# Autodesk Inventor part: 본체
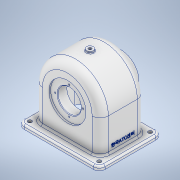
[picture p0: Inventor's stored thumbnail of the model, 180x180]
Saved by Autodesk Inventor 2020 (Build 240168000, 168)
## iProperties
Created: 2022-09
Part Number: 본체
Material: 알루미늄 6061
Document SubType Name: Modeling
Designer: Administrator
Density: 2.7 g/cm^3
Appearance: 알루미늄 - 평지
Mass: 987.342 g
Surface Area: 1165.69 cm^2
Volume: 365.682 cm^3
Author: Administrator
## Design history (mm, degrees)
sketch "스케치1"
  geometry: L1 (-60, 54)-(60, 54); L2 (70, 44)-(70, -44); L3 (60, -54)-(-60, -54); L4 (-70, -44)-(-70, 44); C1 r 3.3 at (-60, 44); C2 r 3.3 at (60, 44); C3 r 3.3 at (60, -44); C4 r 3.3 at (-60, -44); A1 r 10 centre (-60, 44) between (-60, 54) and (-70, 44); A2 r 10 centre (-60, -44) between (-70, -44) and (-60, -54); A3 r 10 centre (60, -44) between (60, -54) and (70, -44); A4 r 10 centre (60, 44) between (70, 44) and (60, 54); 4 further points
  constraints: 8 centre point, 8 end point, 8 point on circle, 8 tangent, 6 point on line, 4 coincident, 3 equal radius, 2 parallel, 1 horizontal, 1 perpendicular
  dimensions: "d0" = 140 distance of point (70, -54) point (-70, -54); "d1" = 108 distance of point (70, 54) point (70, -54); "d2" = 10 radius of A1; "d3" = 6.6 diameter of C1; "d4" = 6.6 diameter of C2; "d5" = 6.6 diameter of C3; "d6" = 6.6 diameter of C4
extrude "돌출1" new body sketch "스케치1" distance "d7" = 7; taper "d8" = 0 deg
sketch "스케치2"
  geometry: L1 (-60, 0)-(60, 0) reference; L2 (-60, 7)-(60, 7) reference; L3 (-63.3, 7)-(-56.7, 7) reference; L4 (-56.7, 64.001)-(-56.7, 7); L5 (57.3, 64)-(57.3, 5.235); A1 r 57 centre (0.3, 64) between (0.6, 120.999) and (-56.7, 64.001); 2 further points
  constraints: 4 end point, 3 point on circle, 1 centre point, 1 perpendicular, 1 tangent, 1 vertical
  dimensions: "d9" = 57 radius of A1; "d10" = 64 distance from line of L1 A1.centre
extrude "돌출2" new body sketch "스케치2" stored distance "d11" = 78; taper "d12" = 0 deg
feature "쉘1" dims "d13" = 5
sketch "스케치3"
  geometry: L1 (57, 7)-(57, 64.001); L2 (-57, 64)-(-57, 7); L3 (-57, 7)-(57, 7); L4 (-60, 0)-(60, 0) reference; C1 r 32 at (0, 64); A1 r 57 centre (0, 64) between (57, 64.001) and (-57, 64); 2 further points
  constraints: 6 end point, 2 centre point, 2 point on circle, 1 coincident, 1 midpoint, 1 vertical alignment
  dimensions: "d14" = 32 radius of C1
sketch "스케치4"
  geometry: C1 r 31 at (-0.3, -64); A1 r 57 centre (-0.3, -64) between (-57.3, -64) and (56.7, -64.001) reference; 1 further point
  constraints: 1 centre point, 1 coincident
  dimensions: "d15" = 62 diameter of C1
extrude "돌출3" join sketch "스케치4" distance "d16" = 15; taper "d17" = 0 deg
feature "결합1"
  node "솔리드2"
sketch "스케치5"
  geometry: C1 r 20 at (0.3, 0); 1 further point
  constraints: 1 centre point
  dimensions: "d18" = 40 diameter of C1
extrude "돌출4" cut sketch "스케치5" distance "d19" = 16; taper "d20" = 0 deg
fillet "모깎기1" dims "d21" = 0.6
sketch "스케치6"
  geometry: C1 r 19.4 at (0, 0) reference; C2 r 17.5 at (0, 0); 1 further point
  constraints: 1 centre point, 1 coincident
  dimensions: "d22" = 35 diameter of C2
extrude "돌출5" cut sketch "스케치6" distance "d23" = 16; taper "d24" = 0 deg
chamfer "모따기1" distance "d25" = 1; stored, may be unused: second distance "d26" = 2, angle "d27" = 45 deg
node "작업 평면1"
sketch "스케치9"
  geometry: L1 (-34, 116)-(-34, 64) reference; L2 (-34, 100.083)-(-20, 92); L3 (-34, 64)-(-34, 12) reference; L4 (-50.325, 64)-(9.78, 64); L5 (-34, 64)-(34, 64) reference; L6 (-20, 92)-(-20, 64); 4 further points
  constraints: 6 end point, 3 point on line, 1 perpendicular
  dimensions: "d35" = 60 deg angle of L6 L2; "d36" = 56 diameter of L2.end L4; "d37" = 14 distance between parallel lines of L1 L6
revolve "회전1" sketch "스케치9" stored, may be unused: angle "d38" = 90 deg
sketch "스케치10"
  geometry: C1 r 28 at (0, 0) reference; C2 r 20 at (0, 0); 1 further point
  constraints: 1 centre point, 1 coincident
  dimensions: "d39" = 40 diameter of C2
extrude "돌출8" cut sketch "스케치10" distance "d40" = 16; taper "d41" = 0 deg
extrude "돌출9" cut sketch "스케치3" stored distance "d42" = 3.25; taper "d43" = 0 deg
fillet "모깎기2" dims "d44" = 14
fillet "모깎기3" dims "d45" = 3
node "작업 평면2"
node "작업 평면3"
sketch "스케치12"
  geometry: C1 r 6 at (0, 0); 1 further point
  constraints: 1 centre point, 1 coincident
  dimensions: "d55" = 12 diameter of C1
extrude "돌출10" join sketch "스케치12" stored distance "d56" = 16; taper "d57" = 0 deg
fillet "모깎기4" dims "d58" = 1
sketch "스케치13"
  geometry: C1 r 6 at (0, 0) reference; 2 further points
  constraints: 1 coincident
hole "구멍2" sketch "스케치13" at (0, 0) diameter "d59" = 5.1881; stored, may be unused: countersink angle "d63" = 90 deg, drill point angle "d65" = 118 deg; dims "d60" = 12, "d61" = 4, "d62" = 2, "d64" = 16
sketch "스케치14"
  geometry: L1 (0.941, 15.484)-(0.941, 34.516); L2 (0.941, 34.516)-(93.06, 34.516); L3 (93.06, 34.516)-(93.06, 15.484); L4 (93.06, 15.484)-(0.941, 15.484); L5 (0, -14)-(54.001, -14) reference; L6 (64.001, -19)-(64.001, 69) reference; 3 further points
  constraints: 2 midpoint, 2 other
  dimensions: "d66" = 39 distance from line of L5 point (0.941, 25); "d67" = 17 distance from line of L6 point (47.001, 34.516)
feature "엠보싱1" sketch "스케치14" dims "d0" = 140, "d1" = 108, "d2" = 10, "d3" = 6.6, "d4" = 6.6, "d5" = 6.6, "d6" = 6.6, "d68" = 0.5, "d69" = 0
chamfer "모따기2" distance "d70" = 1; stored, may be unused: second distance "d71" = 2, angle "d72" = 45 deg
sketch "스케치16" dims "d84" = 48
  geometry: C1 r 21 at (0, 0) reference; 3 further points
  constraints: 1 coincident, 1 vertical alignment, 2 other
hole "구멍4" sketch "스케치16" at (0, 24) diameter "d85" = 2.459; stored, may be unused: countersink angle "d89" = 90 deg, drill point angle "d91" = 118 deg; dims "d86" = 7, "d87" = 4, "d88" = 2, "d90" = 9
node "작업 평면4"
sketch "스케치17"
  geometry: L1 (-51.7, -34)-(-51.7, 34) reference; L2 (52.3, -34)-(-51.7, -34) reference; L3 (-51.7, 34)-(52.3, 34) reference; L4 (52.3, -34)-(52.3, 34) reference; 1 further point
extrude "돌출11" cut sketch "스케치17" distance "d95" = 14.25; taper "d96" = 0 deg
fillet "모깎기5" dims "d97" = 9
node "솔리드1"
pattern_circular "원형 패턴2" dims angle "d93" = 360 deg
mirror "미러2"
feature "A9D066F2-1C7D-4E18-AEED-F7BC21143FA4" dims "d85" = 2.459, "d86" = 7, "d87" = 4, "d88" = 2, "d89" = 90 deg, "d90" = 9, "d91" = 118 deg
other parameters: "d28" = -14, "d54" = -124
